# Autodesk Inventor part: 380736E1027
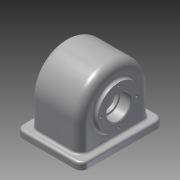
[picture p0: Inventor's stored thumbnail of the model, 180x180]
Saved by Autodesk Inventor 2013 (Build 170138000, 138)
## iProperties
Created: 2018-07
Part Number: 380736E1027
Material: 11111
Document SubType Name: Modeling
Designer: 05-01
Density: 7 g/cm^3
Author: 05-01
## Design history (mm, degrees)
sketch "스케치1"
  geometry: L1 (-51, 0)-(51, 0); L2 (51, 0)-(51, -50); L3 (51, -50)-(-51, -50); L4 (-51, -50)-(-51, 0); A1 r 51 centre (0, 0) between (51, 0) and (-51, 0); 1 further point
  constraints: 8 end point, 2 parallel, 2 point on circle, 2 tangent, 1 centre point, 1 coincident, 1 horizontal, 1 horizontal alignment, 1 perpendicular
  dimensions: "d0" = 102 diameter of A1; "d2" = 101 dimension on A1 L3
extrude "돌출1" new body sketch "스케치1" stored distance "d3" = 74; taper "d4" = 0 deg
fillet "모깎기1" dims "d5" = 12
feature "쉘1" dims "d6" = 9
sketch "스케치2"
  geometry: C1 r 31 at (0, 0); A1 r 39 centre (0, 0) between (0, 39) and (0, -39) reference
  constraints: 1 centre point, 1 coincident
  dimensions: "d7" = 62 diameter of C1
extrude "돌출2" join sketch "스케치2" distance "d9" = 5; taper "d10" = 0 deg
sketch "스케치3"
  geometry: C1 r 31 at (0, 0) reference; C2 r 31 at (0, 0) reference
extrude "돌출3" join sketch "스케치3" distance "d11" = 20; taper "d12" = 0 deg
hole "구멍1" diameter "d15" = 29; stored, may be unused: countersink angle "d19" = 90 deg, drill point angle "d21" = 118 deg; dims "d16" = 6, "d17" = 35, "d18" = 15, "d20" = 30, "d22" = 10, "d23" = 10
hole "구멍2" diameter "d26" = 36; stored, may be unused: countersink angle "d30" = 90 deg, drill point angle "d32" = 118 deg; dims "d24" = 10, "d25" = 10, "d27" = 6, "d28" = 42, "d29" = 15, "d31" = 25
sketch "스케치4"
  geometry: L1 (50, 0)-(0, 0) reference; L2 (-12, -90)-(-12, -12) reference; L3 (50, -102)-(0, -102) reference; L4 (62, -12)-(62, -90) reference; L5 (-22.5, 9)-(72.5, 9); L6 (72.5, 9)-(72.5, -111); L7 (72.5, -111)-(-22.5, -111); L8 (-22.5, -111)-(-22.5, 9); A1 r 12 centre (50, -12) between (62, -12) and (50, 0) reference; A2 r 12 centre (0, -12) between (0, 0) and (-12, -12) reference; A3 r 12 centre (0, -90) between (-12, -90) and (0, -102) reference; A4 r 12 centre (50, -90) between (50, -102) and (62, -90) reference; 3 further points
  constraints: 8 end point, 2 midpoint, 2 parallel, 1 horizontal, 1 horizontal alignment, 1 perpendicular, 1 vertical alignment
  dimensions: "d33" = 95 distance of L6.end L7.end; "d35" = 120 distance of L5.end L6.end
extrude "돌출4" join sketch "스케치4" distance "d36" = 10; taper "d37" = 0 deg
sketch "스케치5"
  geometry: C1 r 17.5 at (0, 0) reference; 1 further point
  constraints: 1 vertical alignment
  dimensions: "d38" = 26 distance of point (0, 26) C1.centre
hole "구멍3" sketch "스케치5" at (0, 26) diameter "d39" = 3.242; stored, may be unused: countersink angle "d43" = 90 deg, drill point angle "d45" = 118 deg; dims "d40" = 8, "d41" = 42, "d42" = 15, "d44" = 10
fillet "모깎기2" dims "d49" = 10
fillet "모깎기3" dims "d50" = 3
fillet "모깎기4" dims "d51" = 3
chamfer "모따기1" distance "d52" = 1; stored, may be unused: second distance "d53" = 2, angle "d54" = 45 deg
node "솔리드1"
mirror "대칭1"
pattern_circular "원형 패턴1" dims angle "d47" = 360 deg
mirror "대칭2"
node "절단 모서리 투영1"
